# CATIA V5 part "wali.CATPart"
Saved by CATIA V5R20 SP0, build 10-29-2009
Part number: Part1
Bounding box of the stored display mesh (mm): x -210 to 500, y -380 to 380, z -300 to 187.23
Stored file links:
  C:\Users\86155\Desktop\wali.CATPart
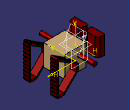
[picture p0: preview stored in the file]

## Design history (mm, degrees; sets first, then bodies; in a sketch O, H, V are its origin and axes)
Body1 (main body)
Body2
Body3
Body4
Body5
  Sketch1 on xy-plane, origin (0, 0, 0), H (1, 0, 0), V (0, 1, 0)
    line L1 (-190, -10) -> (-110, -50)
    line L2 (-110, -50) -> (-110, -200)
    line L3 (-110, -200) -> (-210, -220)
    line L4 (-210, -220) -> (-210, -10)
    line L5 (-210, -10) -> (-190, -10)
    vertical: L2 V, L4 V
    horizontal: L5 H
  Pad1: profile Sketch1, direction (0, 0, -1), length 125, mirrored extent
  Sketch2 on end face of Pad1, origin (-156.9633, -122.8447, -125), H (1, 0, 0), V (0, -1, 0)
    point P1 (0, -30)
  Hole1: placed by Sketch2, at (-156.9633, -92.8447, -125) direction (0, 0, 1), diameter 86, depth 31
  Fillet1: radius 26, on edge [face of Pad1 from Sketch1.L1 | face of Pad1 from Sketch1.L5]
  Fillet2: radius 26, on edge [face of Pad1 from Sketch1.L5 | face of Pad1 from Sketch1.L4]
  Fillet3: radius 26, on edge [face of Pad1 from Sketch1.L2 | face of Pad1 from Sketch1.L1]
  Fillet4: radius 42, on edge [face of Pad1 from Sketch1.L3 | face of Pad1 from Sketch1.L2]
  Fillet5: radius 14, on edge [face of Pad1 from Sketch1.L4 | face of Pad1 from Sketch1.L3]
  Sketch3 on start face of Pad1, origin (0, 0, 125), H (1, 0, 0), V (0, 1, 0)
    line L1 (-190, -190) -> (-190, -50)
    line L2 (-190, -50) -> (-180, -40)
    line L3 (-180, -40) -> (-130, -50)
    line L4 (-130, -50) -> (-130, -170)
    line L5 (-130, -170) -> (-190, -190)
    vertical: L1 V, L4 V
  Mirror1: of the body so far, about zx-plane
  Sketch4 on xy-plane, origin (0, 0, 0), H (1, 0, 0), V (0, 1, 0)
    line L1 (100, 160) -> (100, 380)
    point P1 (100, 160)
    vertical: L1 V
  Plane1: type Normal, Curve Sketch4, RefPoint Sketch4.P1
  Circle1: type CtrRad, Start 0, End 180, Center Sketch4.P1, Support Plane1, Radius 30, FirstDirection (-1, 0, 0)
  Rib1: profile Circle1, centre curve Sketch4
  Pocket1: profile Sketch3, direction (0, 0, -1), length 20
  Sketch5 on end face of Pocket1, origin (-154.1154, -90.6644, 105), H (1, 0, 0), V (0, 1, 0)
    point P1 (0, 0)
  Hole2: placed by Sketch5, at (-154.1154, -90.6644, 105) direction (0, 0, -1), diameter 76, depth 29
  Mirror2: of the body so far, about zx-plane
  Sketch6 on face of Pad5 from Sketch20.L4, origin (0, -147.9409, 0), H (1, 0, 0), V (0, 0, 1)
    line L1 (200, -100) -> (400, -300)
    line L2 (400, -300) -> (500, -300)
    line L3 (500, -300) -> (500, 200)
    line L4 (500, 200) -> (200, 0)
    point P5 (200, 0)
    line L5 (200, 0) -> (200, -100)
    line L6 (230, -100) -> (400, -270)
    line L7 (400, -270) -> (480, -270)
    line L8 (480, -270) -> (480, 150)
    line L9 (480, 150) -> (230, 0)
    point P10 (230, 0)
    line L10 (230, 0) -> (230, -100)
    horizontal: L2 H, L7 H
    vertical: L3 V, L5 V, L8 V, L10 V
    coincidence: P5 H, P10 H
    parallelism: L6 L1
  Pad2: profile Sketch6, direction (0, -1, 0), length 95
  Fillet6: radius 17, on edge [face of Pad2 from Sketch6.L1 | end face of Pad2]; edge [face of Pad2 from Sketch6.L2 | face of Pad2 from Sketch6.L1]; edge [face of Pad2 from Sketch6.L1 | face of Pad2 from Sketch6.L5]; edge [face of Pad2 from Sketch6.L5 | face of Pad2 from Sketch6.L4]; edge [face of Pad2 from Sketch6.L4 | face of Pad2 from Sketch6.L3]; edge [face of Pad2 from Sketch6.L3 | face of Pad2 from Sketch6.L2]
  Fillet7: radius 17, on edge [face of Pad2 from Sketch6.L5 | end face of Pad2]
  Mirror3: of the body so far, about zx-plane
  Sketch7 on face of Pad2 from Sketch6.L1, origin (50, 0, 50), H (0, -1, 0), V (-0.7071, 0, 0.7071)
    line L1 (100, -400) -> (290, -400)
    line L2 (290, -400) -> (290, -420)
    line L3 (290, -420) -> (100, -420)
    line L4 (100, -420) -> (100, -400)
    horizontal: L1 H, L3 H
    vertical: L2 V, L4 V
  Pocket2: profile Sketch7, direction (0.7071, 0, 0.7071), length 6
  RectPattern1: of Pocket2, direction 1 instances 5, spacing 45, along edge [face of Pad2 from Sketch6.L6 | start face of Pad2] reversed
  RectPattern2: of Pocket2, direction 1 instances 5, spacing 45, along axis of face of Fillet6
  Sketch8 on face of Pad2 from Sketch6.L3, origin (500, 0, 0), H (0, 1, 0), V (0, 0, 1)
    line L1 (-290, 100) -> (-120, 100)
    line L2 (-120, 100) -> (-120, 80)
    line L3 (-120, 80) -> (-290, 80)
    line L4 (-290, 80) -> (-290, 100)
    horizontal: L1 H, L3 H
    vertical: L2 V, L4 V
  Pocket3: profile Sketch8, direction (-1, 0, 0), length 6
  RectPattern3: of Pocket3, direction 1 instances 5, spacing 45, along face of Pad2 from Sketch6.L3
  RectPattern4: of Pocket3, direction 1 instances 10, spacing 45, along face of Pad2 from Sketch6.L3 reversed
  Sketch9 on face of Pad2 from Sketch6.L2, origin (0, 0, -300), H (1, 0, 0), V (0, -1, 0)
    line L1 (420, 280) -> (420, 120)
    line L2 (420, 120) -> (440, 120)
    line L3 (440, 120) -> (440, 280)
    line L4 (440, 280) -> (420, 280)
    vertical: L1 V, L3 V
    horizontal: L2 H, L4 H
  Pocket4: profile Sketch9, direction (0, 0, 1), length 6
  RectPattern5: of Pocket4, direction 1 instances 3, spacing 45, along face of Pad2 from Sketch6.L2
  Sketch10 on face of Pad2 from Sketch6.L4, origin (61.5385, 0, -92.3077), H (0, -1, 0), V (0.8321, 0, 0.5547)
    line L1 (100, 460) -> (300, 460)
    line L2 (300, 460) -> (300, 440)
    line L3 (300, 440) -> (100, 440)
    line L4 (100, 440) -> (100, 460)
    horizontal: L1 H, L3 H
    vertical: L2 V, L4 V
  Pocket5: profile Sketch10, direction (0.5547, 0, -0.8321), length 6
  RectPattern6: of Pocket5, direction 1 instances 7, spacing 45, along face of Pad2 from Sketch6.L4
  RectPattern7: of Pocket5, direction 1 instances 7, spacing 45, along axis of face of Fillet7
  Mirror4: of Pad2, about zx-plane
  Mirror5: of Pad2, about zx-plane
  Mirror6: of Pad2, about zx-plane
  Mirror7: of Pad2, about zx-plane
  Mirror8: of Pocket4, about zx-plane
  Sketch11 on face of Mirror7, origin (50, 0, 50), H (0, -1, 0), V (-0.7071, 0, 0.7071)
    line L1 (-300, -460) -> (-100, -460)
    line L2 (-100, -460) -> (-100, -480)
    line L3 (-100, -480) -> (-300, -480)
    line L4 (-300, -480) -> (-300, -460)
    horizontal: L1 H, L3 H
    vertical: L2 V, L4 V
  Pocket6: profile Sketch11, direction (0.7071, 0, 0.7071), length 6
  RectPattern8: of Pocket6, direction 1 instances 7, spacing 45, along face of Mirror7 reversed
  Sketch12 on face of Mirror7, origin (0, 0, -300), H (1, 0, 0), V (0, -1, 0)
    line L1 (410, -120) -> (410, -270)
    line L2 (410, -270) -> (430, -270)
    line L3 (430, -270) -> (430, -120)
    line L4 (430, -120) -> (410, -120)
    vertical: L1 V, L3 V
    horizontal: L2 H, L4 H
  Pocket7: profile Sketch12, direction (0, 0, 1), length 6
  RectPattern9: of Pocket7, direction 1 instances 7, spacing 45, along face of Mirror7
  Fillet8: radius 17, on edge [face of Mirror7 | face of Mirror7]
  Sketch13 on face of Mirror7, origin (500, 0, 0), H (0, 1, 0), V (0, 0, 1)
    line L1 (120, -270) -> (290, -270)
    line L2 (290, -270) -> (290, -290)
    line L3 (290, -290) -> (120, -290)
    line L4 (120, -290) -> (120, -270)
    horizontal: L1 H, L3 H
    vertical: L2 V, L4 V
  Pocket8: profile Sketch13, direction (-1, 0, 0), length 6
  RectPattern10: of Pocket8, direction 1 instances 14, spacing 45, along face of Mirror7
  Sketch14 on face of Mirror7, origin (61.5385, 0, -92.3077), H (0, -1, 0), V (0.8321, 0, 0.5547)
    line L1 (-250, 490) -> (-250, 470)
    line L2 (-250, 470) -> (-120, 470)
    line L3 (-120, 470) -> (-120, 490)
    line L4 (-120, 490) -> (-250, 490)
    vertical: L1 V, L3 V
    horizontal: L2 H, L4 H
  Pocket9: profile Sketch14, direction (0.5547, 0, -0.8321), length 6
  RectPattern11: of Pocket9, direction 1 instances 14, spacing 45, along face of Mirror7
  Fillet9: radius 17, on edge [face of Mirror7 | face of Mirror7]
  Sketch15 on face of Pad5 from Sketch20.L3, origin (0, 0, -200), H (1, 0, 0), V (0, -1, 0)
  Sketch16 on end face of Pad1, origin (0, 0, -125), H (1, 0, 0), V (0, 1, 0)
    line L1 (-190, -10) -> (-110, -50)
    line L2 (-110, -50) -> (-110, -200)
    line L3 (-110, -200) -> (-210, -220)
    line L4 (-210, -220) -> (-210, -10)
    line L5 (-210, -10) -> (-190, -10)
    vertical: L2 V, L4 V
    horizontal: L5 H
  Pad3: profile Sketch16, direction (0, 0, -1), length 70, mirrored extent
  Sketch17 on end face of Pad3, origin (0, 0, -195), H (1, 0, 0), V (0, 1, 0)
    line L1 (-190, -10) -> (-110, -50)
    line L2 (-110, -50) -> (-110, -200)
    line L3 (-110, -200) -> (-210, -220)
    line L4 (-210, -220) -> (-210, -10)
    line L5 (-210, -10) -> (-190, -10)
    vertical: L2 V, L4 V
    horizontal: L5 H
  Pad4: profile Sketch17, direction (0, 0, -1), length 70, mirrored extent
Body6
  Sketch18 on zx-plane, origin (0, 0, 0), H (-1, 0, 0), V (0, 0, 1)
    point P1 (0, 70)
    line L1 (0, 70) -> (80, 30)
    line L2 (80, 30) -> (160, 30)
    coincidence: P1 V
    horizontal: L2 H
  Plane2: type Normal, Curve Sketch18, RefPoint Sketch18.P1
  Circle2: type CtrRad, Start 0, End 180, Center Sketch18.P1, Support Plane2, Radius 15, FirstDirection (0, -1, 0)
  Rib2: profile Circle2, centre curve Sketch18
Body7
  Sketch19 on yz-plane, origin (0, 0, 0), H (0, 1, 0), V (0, 0, 1)
  Sketch20 on yz-plane, origin (0, 0, 0), H (0, 1, 0), V (0, 0, 1)
    line L1 (-147.9409, 100) -> (152.0591, 100)
    line L2 (152.0591, 100) -> (152.0591, -200)
    line L3 (152.0591, -200) -> (-147.9409, -200)
    line L4 (-147.9409, -200) -> (-147.9409, 100)
    length L2 = 300
    length L1 = 300
    horizontal: L1 H, L3 H
    vertical: L2 V, L4 V
  Pad5: profile Sketch20, direction (1, 0, 0), length 300
  Sketch21 on start face of Pad5, origin (0, 0, 0), H (0, 1, 0), V (0, 0, 1)
    line L1 (-101.0835, 100) -> (98.9165, 100)
    line L2 (98.9165, 100) -> (98.9165, -100)
    line L3 (98.9165, -100) -> (-101.0835, -100)
    line L4 (-101.0835, -100) -> (-101.0835, 100)
    length L2 = 200
    length L1 = 200
    horizontal: L1 H, L3 H
    vertical: L2 V, L4 V
  Pad6: profile Sketch21, direction (1, 0, 0), length 200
